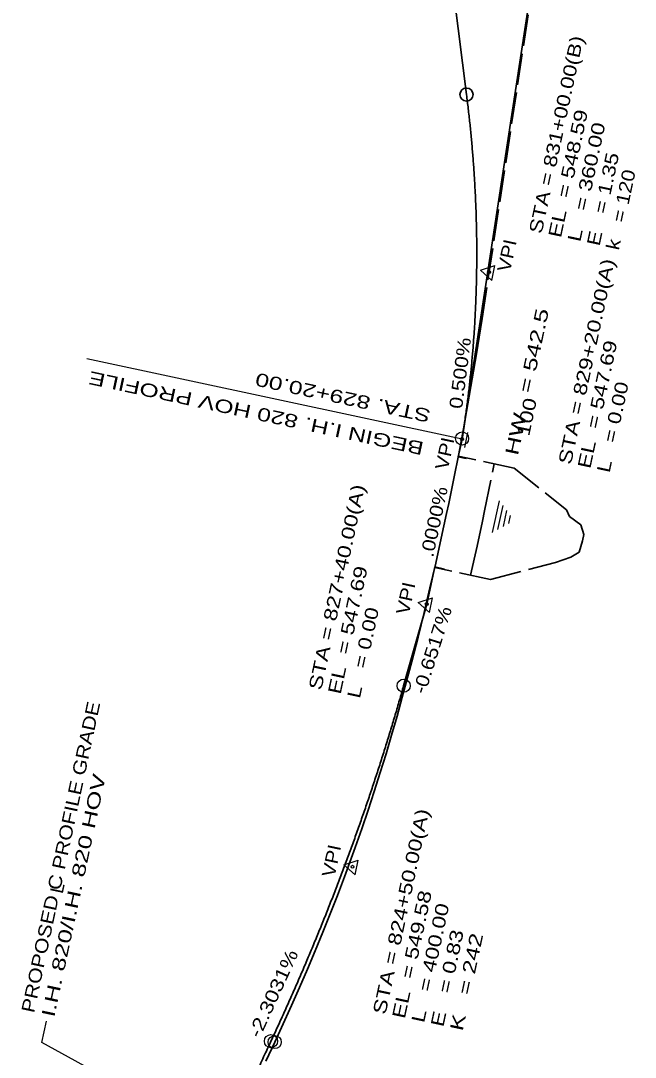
# Model space of a CAD drawing. Extents: x 2363411 to 2369702, y 6977197 to 6988655.
# Drawn here: x 2367135 to 2367789, y 6982449 to 6983553 of the extents above; entities that cross this region are included whole.
import ezdxf
from ezdxf.enums import TextEntityAlignment as Align

# ---------------------------------------------------------------- set-up
doc = ezdxf.new("R2010")
doc.units = 0
doc.header["$LTSCALE"] = 5.6
doc.linetypes.add('LONG_DASHED', pattern=[7.5, 6, -1.5])
for name, color, linetype, lineweight in [('44', 7, 'Continuous', 25), ('58', 7, 'Continuous', 25), ('61', 7, 'Continuous', 25)]:
    doc.layers.add(name, color=color, linetype=linetype, lineweight=lineweight)
doc.layers.add('50', color=7, linetype='Continuous')

msp = doc.modelspace()

# ---------------------------------------------------------------- linework, layer by layer
at = {"layer": '44', "lineweight": 35}
for p, q in [((2367604.934, 6983107.709), (2367774.368, 6984214.683)), ((2367609.745, 6983474.807), (2367553.751, 6983916.249)), ((2367600.897, 6983088.814), (2367604.934, 6983107.709)), ((2367600.897, 6983088.814), (2367609.339, 6983087.01)), ((2367567.322, 6982931.683), (2367575.821, 6982971.458)), ((2367575.821, 6982971.458), (2367586.306, 6982969.218)), ((2367542.782, 6982844.894), (2367567.322, 6982931.683))]:
    msp.add_line(p, q, dxfattribs=at)
at = {"layer": '44', "linetype": 'LONG_DASHED', "lineweight": 35}
for p, q in [((2367660.565, 6983076.72), (2367600.901, 6983089.468)), ((2367660.565, 6983076.72), (2367716.312, 6983032.176)), ((2367635.223, 6982958.112), (2367704.462, 6982976.024)), ((2367635.223, 6982958.112), (2367575.806, 6982970.807))]:
    msp.add_line(p, q, dxfattribs=at)
at = {"layer": '44'}
for p, q in [((2367644.341, 6983042.041), (2367637.087, 6983008.09)), ((2367648.331, 6983036.785), (2367642.877, 6983011.258)), ((2367652.321, 6983031.528), (2367648.666, 6983014.425)), ((2367656.31, 6983026.269), (2367654.456, 6983017.593)), ((2367558.206, 6982933.667), (2367573.59, 6982938.604)), ((2367558.206, 6982933.667), (2367570.17, 6982922.809)), ((2367570.17, 6982922.809), (2367573.59, 6982938.604)), ((2367479.121, 6982653.981), (2367494.485, 6982658.979)), ((2367491.127, 6982643.17), (2367494.485, 6982658.979)), ((2367479.121, 6982653.981), (2367491.127, 6982643.17))]:
    msp.add_line(p, q, dxfattribs=at)
at = {"layer": '44', "linetype": 'LONG_DASHED', "lineweight": 35}
for points in [[(2367395.853, 6982444.663), (2367405.406, 6982465.107), (2367414.437, 6982484.501), (2367423.272, 6982503.935), (2367431.912, 6982523.413), (2367440.357, 6982542.931), (2367448.606, 6982562.492), (2367456.659, 6982582.095), (2367464.516, 6982601.739), (2367472.178, 6982621.425), (2367479.644, 6982641.152), (2367483.969, 6982652.844), (2367491.124, 6982672.639), (2367498.084, 6982692.474), (2367504.848, 6982712.353), (2367511.416, 6982732.272), (2367517.789, 6982752.234), (2367523.966, 6982772.237), (2367529.948, 6982792.282), (2367535.733, 6982812.369), (2367541.323, 6982832.498), (2367544.538, 6982844.426), (2367551.404, 6982870.578), (2367558.076, 6982896.773), (2367564.551, 6982923.009), (2367570.831, 6982949.286), (2367576.915, 6982975.606), (2367582.805, 6983001.967), (2367588.497, 6983028.372), (2367590.748, 6983039.076), (2367596.166, 6983065.538), (2367601.389, 6983092.043), (2367606.416, 6983118.587), (2367611.248, 6983145.174), (2367615.883, 6983171.804), (2367620.323, 6983198.475), (2367624.569, 6983225.188), (2367626.232, 6983236.018), (2367778.265, 6984235.836)], [(2367614.006, 6982962.645), (2367620.922, 6982993.601), (2367626.665, 6983020.245), (2367628.958, 6983031.147), (2367639.223, 6983081.28)], [(2367704.462, 6982976.024), (2367720.678, 6982981.97), (2367729.622, 6982987.043), (2367733.134, 6982999.388), (2367734.561, 6983006.068), (2367731.511, 6983016.323), (2367719.395, 6983025.023), (2367716.312, 6983032.176)]]:
    msp.add_lwpolyline(points, dxfattribs=at)
at = {"layer": '44', "lineweight": 35}
msp.add_circle((2367609.746, 6983474.807), 7, dxfattribs=at)
at = {"layer": '44'}
for centre in [(2367604.988, 6983108.299), (2367542.778, 6982844.895), (2367401.409, 6982466.073), (2367405.405, 6982465.107)]:
    msp.add_circle(centre, 7, dxfattribs=at)
at = {"layer": '44', "lineweight": 35}
for points in [[(2367604.933, 6983107.709), (2367606.066, 6983114.829), (2367607.154, 6983121.96), (2367608.201, 6983129.098), (2367609.206, 6983136.246), (2367610.167, 6983143.403), (2367611.089, 6983150.569), (2367611.965, 6983157.744), (2367612.801, 6983164.928), (2367613.595, 6983172.121), (2367614.345, 6983179.323), (2367615.055, 6983186.534), (2367615.721, 6983193.754), (2367616.345, 6983200.983), (2367616.928, 6983208.221), (2367617.466, 6983215.469), (2367617.966, 6983222.725), (2367618.42, 6983229.99), (2367618.833, 6983237.264), (2367619.205, 6983244.547), (2367619.532, 6983251.84), (2367619.82, 6983259.141), (2367620.063, 6983266.452), (2367620.265, 6983273.771), (2367620.425, 6983281.099), (2367620.541, 6983288.437), (2367620.618, 6983295.783), (2367620.649, 6983303.139), (2367620.64, 6983310.503), (2367620.59, 6983317.877), (2367620.494, 6983325.26), (2367620.36, 6983332.651), (2367620.18, 6983340.052), (2367619.96, 6983347.462), (2367619.698, 6983354.88), (2367619.391, 6983362.308), (2367619.045, 6983369.744), (2367618.655, 6983377.19), (2367618.223, 6983384.645), (2367617.75, 6983392.109), (2367617.232, 6983399.582), (2367616.675, 6983407.063), (2367616.073, 6983414.555), (2367615.43, 6983422.055), (2367614.746, 6983429.563), (2367614.017, 6983437.082), (2367613.248, 6983444.608), (2367612.435, 6983452.145), (2367611.581, 6983459.69), (2367610.685, 6983467.243), (2367609.745, 6983474.807)], [(2367401.41, 6982466.072), (2367404.869, 6982473.514), (2367408.305, 6982480.96), (2367411.713, 6982488.413), (2367415.096, 6982495.87), (2367418.454, 6982503.333), (2367421.784, 6982510.802), (2367425.091, 6982518.277), (2367428.37, 6982525.756), (2367431.624, 6982533.242), (2367434.85, 6982540.733), (2367438.053, 6982548.229), (2367441.229, 6982555.731), (2367444.379, 6982563.239), (2367447.504, 6982570.752), (2367450.604, 6982578.27), (2367453.676, 6982585.794), (2367456.724, 6982593.323), (2367459.745, 6982600.858), (2367462.741, 6982608.399), (2367465.709, 6982615.945), (2367468.654, 6982623.496), (2367471.572, 6982631.054), (2367474.464, 6982638.616), (2367477.33, 6982646.184), (2367480.17, 6982653.758), (2367482.984, 6982661.338), (2367485.774, 6982668.922), (2367488.537, 6982676.512), (2367491.272, 6982684.108), (2367493.985, 6982691.709), (2367496.669, 6982699.316), (2367499.329, 6982706.929), (2367501.963, 6982714.546), (2367504.571, 6982722.17), (2367507.152, 6982729.799), (2367509.708, 6982737.433), (2367512.238, 6982745.073), (2367514.743, 6982752.719), (2367517.222, 6982760.369), (2367519.674, 6982768.026), (2367522.101, 6982775.688), (2367524.502, 6982783.356), (2367526.878, 6982791.029), (2367529.228, 6982798.707), (2367531.551, 6982806.391), (2367533.848, 6982814.081), (2367536.12, 6982821.776), (2367538.367, 6982829.477), (2367540.586, 6982837.183), (2367542.782, 6982844.894)], [(2367134.884, 6981602.705), (2367137.779, 6981620.493), (2367140.773, 6981638.26), (2367143.868, 6981656.005), (2367147.062, 6981673.729), (2367150.355, 6981691.431), (2367153.747, 6981709.113), (2367157.24, 6981726.773), (2367160.831, 6981744.412), (2367164.522, 6981762.029), (2367168.312, 6981779.626), (2367172.2, 6981797.201), (2367176.19, 6981814.755), (2367180.278, 6981832.288), (2367184.466, 6981849.8), (2367188.753, 6981867.29), (2367193.138, 6981884.759), (2367197.625, 6981902.207), (2367202.209, 6981919.634), (2367206.893, 6981937.039), (2367211.678, 6981954.423), (2367216.561, 6981971.786), (2367221.545, 6981989.127), (2367226.626, 6982006.448), (2367231.807, 6982023.747), (2367237.088, 6982041.025), (2367242.469, 6982058.282), (2367247.949, 6982075.517), (2367253.527, 6982092.732), (2367259.205, 6982109.925), (2367264.983, 6982127.096), (2367270.86, 6982144.247), (2367276.837, 6982161.376), (2367282.912, 6982178.484), (2367289.089, 6982195.571), (2367295.363, 6982212.637), (2367301.737, 6982229.681), (2367308.211, 6982246.704), (2367314.783, 6982263.706), (2367321.456, 6982280.687), (2367328.227, 6982297.646), (2367335.098, 6982314.584), (2367342.069, 6982331.501), (2367349.137, 6982348.397), (2367356.308, 6982365.271), (2367363.576, 6982382.125), (2367370.943, 6982398.957), (2367378.411, 6982415.768), (2367385.978, 6982432.557), (2367393.643, 6982449.326), (2367401.41, 6982466.072)]]:
    msp.add_spline(points, degree=3, dxfattribs=at)
at = {"layer": '58'}
for p, q in [((2367624.628, 6983287.607), (2367640.014, 6983292.534)), ((2367624.628, 6983287.607), (2367636.583, 6983276.741)), ((2367636.583, 6983276.741), (2367640.014, 6983292.534)), ((2367607.781, 6983098.836), (2367611.201, 6983114.631))]:
    msp.add_line(p, q, dxfattribs=at)
for centre in [(2367633.744, 6983285.617), (2367604.934, 6983107.71), (2367604.934, 6983107.709), (2367567.323, 6982931.683), (2367488.245, 6982652.033)]:
    msp.add_circle(centre, 1.5, dxfattribs=at)
at = {"layer": '61'}
for p, q in [((2367604.931, 6983107.709), (2367205.336, 6983193.09)), ((2367157.409, 6982464.85), (2367162.243, 6982487.474)), ((2367351.13, 6982358.149), (2367157.409, 6982464.85))]:
    msp.add_line(p, q, dxfattribs=at)

# ---------------------------------------------------------------- texts
at = {"layer": '44'}
for s, rotation, width, p in [('STA = 831+00.00(B)', 77.939, 1.25, (2367689.754, 6983325.824)), ('EL  = 548.59', 77.939, 1.3, (2367710.291, 6983321.436)), ('L   = 360.00', 77.939, 1.3, (2367730.828, 6983317.048)), ('E   = 1.35', 77.939, 1.25, (2367751.366, 6983312.66)), ('k   = 120', 77.939, 1.2, (2367771.903, 6983308.272)), ('STA = 829+20.00(A)', 77.939, 1.3, (2367721.007, 6983079.811)), ('EL  = 547.69', 77.939, 1.3, (2367741.544, 6983075.423)), ('L   = 0.00', 77.939, 1.25, (2367762.081, 6983071.035)), ('STA = 827+40.00(A)', 77.939, 1.3, (2367455.035, 6982839.373)), ('.0000%', 77.939, 1.2, (2367574.098, 6982980.877)), ('EL  = 547.69', 77.939, 1.3, (2367475.572, 6982834.985)), ('L   = 0.00', 77.939, 1.25, (2367496.109, 6982830.597)), ('-0.6517%', 72.529, 1.2, (2367565.621, 6982834.999)), ('STA = 824+50.00(A)', 77.939, 1.3, (2367523.407, 6982493.702)), ('EL  = 549.58', 77.939, 1.3, (2367543.944, 6982489.314)), ('L   = 400.00', 77.939, 1.3, (2367564.481, 6982484.926)), ('E   = 0.83', 77.939, 1.3, (2367585.019, 6982480.538)), ('K   = 242', 77.939, 1.4, (2367605.556, 6982476.15)), ('-2.3031%', 65.473, 1.25, (2367389.45, 6982468.516))]:
    msp.add_text(s, height=14, rotation=rotation, dxfattribs=dict(at, width=width)).set_placement(p)
for s, rotation, width, p in [('HW   = 542.5', 77.939, 1.45, (2367681.025, 6983167.351)), ('100', 77.939, 1.3, (2367680.615, 6983129.897)), ('VPI', 77.781, 1.15, (2367593.357, 6983090.852)), ('VPI', 77.781, 1.15, (2367551.811, 6982936.595)), ('VPI', 78.008, 1.15, (2367472.708, 6982656.856))]:
    msp.add_text(s, height=14, rotation=rotation, dxfattribs=dict(at, width=width)).set_placement(p, align=Align.CENTER)
at = {"layer": '50', "width": 1.2}
msp.add_text('0.500%', height=14, rotation=82.672, dxfattribs=at).set_placement((2367605.016, 6983139.329))
at = {"layer": '58', "width": 1.15}
msp.add_text('VPI', height=14, rotation=77.744, dxfattribs=at).set_placement((2367659.663, 6983301.801), align=Align.CENTER)
at = {"layer": '61'}
for s, rotation, width, p in [('BEGIN I.H. 820 HOV PROFILE', 167.939, 1.4, (2367565.154, 6983104.146)), ('STA. 829+20.00', 167.939, 1.4, (2367572.565, 6983138.829)), ('PROPOSED C PROFILE GRADE', 77.939, 1.2, (2367149.016, 6982495.45)), ('I.H. 820/I.H. 820 HOV', 77.939, 1.45, (2367170.531, 6982490.853))]:
    msp.add_text(s, height=14, rotation=rotation, dxfattribs=dict(at, width=width)).set_placement(p)
at = {"layer": '61', "width": 1.05}
msp.add_text('L', height=14, rotation=77.939, dxfattribs=at).set_placement((2367180.667, 6982627.866), align=Align.CENTER)

doc.saveas('drawing.dxf')
